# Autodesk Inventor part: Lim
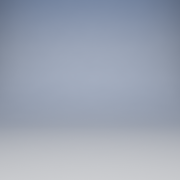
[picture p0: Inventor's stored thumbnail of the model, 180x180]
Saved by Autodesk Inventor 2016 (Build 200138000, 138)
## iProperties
Created: 2015-08
Part Number: Lim
Material: Generic
Document SubType Name: Modeling
Designer: stank
Density: 1 g/cm^3
Appearance: Default
Author: stank
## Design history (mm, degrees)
